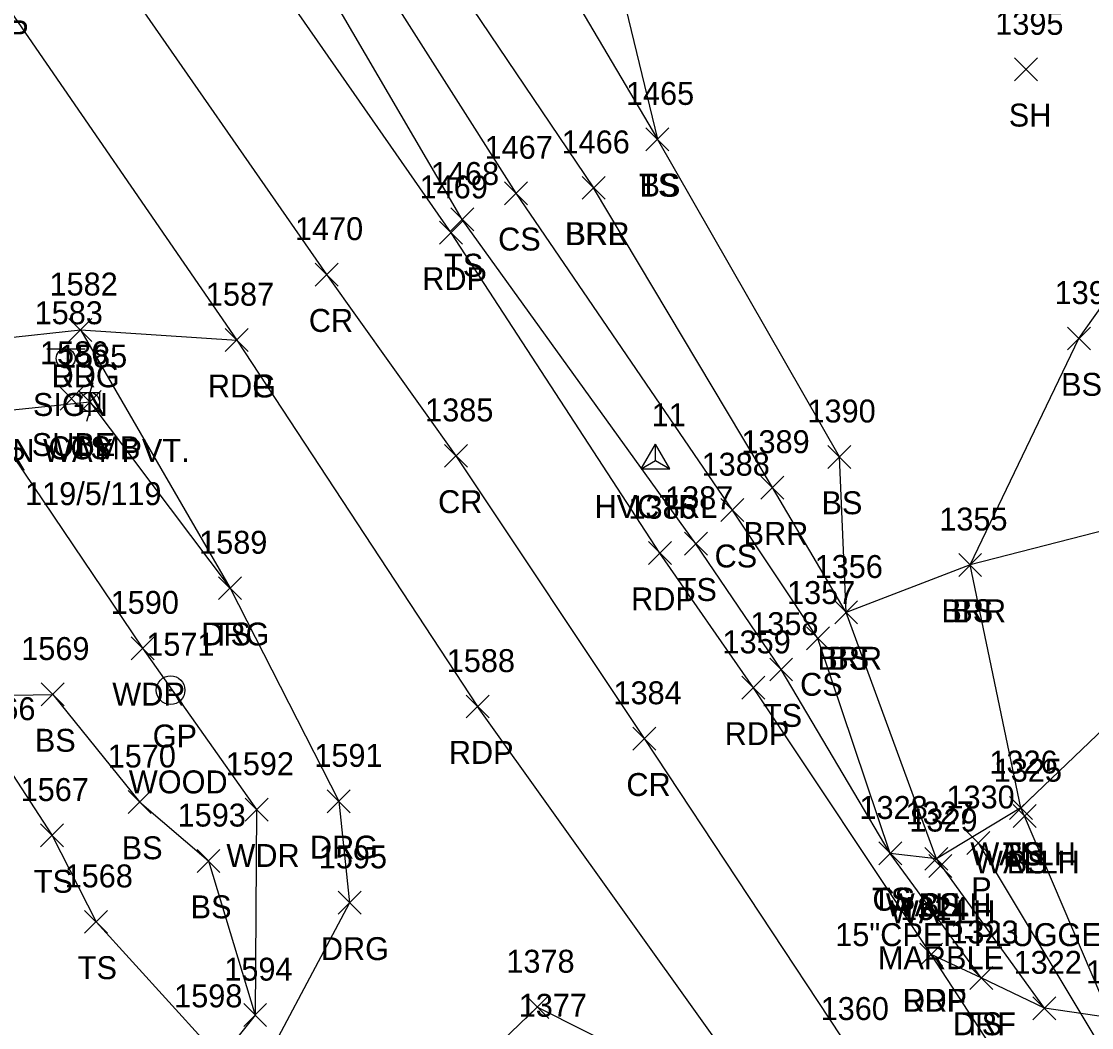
# Model space of a CAD drawing. Extents: x 1501299 to 1502485, y 381423 to 383765.
# Drawn here: x 1501656.9 to 1501750.2, y 383138.3 to 383226.1 of the extents above; entities that cross this region are included whole.
import ezdxf

# ---------------------------------------------------------------- set-up
doc = ezdxf.new("R2010")
doc.units = 0
for name, color, linetype in [('C_A', 7, 'Continuous'), ('C_I', 7, 'Continuous'), ('CPSM', 7, 'Continuous'), ('D_A', 7, 'Continuous'), ('D_C', 7, 'Continuous'), ('D_I', 7, 'Continuous'), ('D_TIC', 7, 'Continuous'), ('DCP', 7, 'Continuous'), ('DHW', 7, 'Continuous'), ('L_A', 7, 'Continuous'), ('L_I', 7, 'Continuous'), ('L_TIC', 7, 'Continuous'), ('LABL', 7, 'Continuous'), ('LAWA', 7, 'Continuous'), ('LELB', 7, 'Continuous'), ('P_A', 7, 'Continuous'), ('P_I', 7, 'Continuous'), ('P_TIC', 7, 'Continuous'), ('PET', 7, 'Continuous'), ('PEU', 7, 'Continuous'), ('PRC', 7, 'Continuous'), ('R_A', 7, 'Continuous'), ('R_C', 7, 'Continuous'), ('R_I', 7, 'Continuous'), ('R_TIC', 7, 'Continuous'), ('RDF', 7, 'Continuous'), ('RDG', 7, 'Continuous'), ('RGP', 7, 'Continuous'), ('S_A', 7, 'Continuous'), ('S_C', 7, 'Continuous'), ('S_I', 7, 'Continuous'), ('SSGN', 7, 'Continuous'), ('U_A', 7, 'Continuous'), ('U_C', 7, 'Continuous'), ('U_I', 7, 'Continuous'), ('U_TIC', 7, 'Continuous'), ('UP', 7, 'Continuous')]:
    doc.layers.add(name, color=color, linetype=linetype)

msp = doc.modelspace()

# ---------------------------------------------------------------- linework, layer by layer
at = {"layer": 'CPSM'}
for p, q in [((1501710.948, 383187.056), (1501712.198, 383189.221)), ((1501713.448, 383187.056), (1501712.198, 383189.221)), ((1501712.198, 383187.777), (1501712.198, 383189.221)), ((1501710.948, 383187.056), (1501712.198, 383187.777)), ((1501712.198, 383187.777), (1501712.198, 383187.777)), ((1501712.198, 383187.777), (1501713.448, 383187.056)), ((1501710.948, 383187.056), (1501713.448, 383187.056))]:
    msp.add_line(p, q, dxfattribs=at)
at = {"layer": 'D_TIC'}
for points in [[(1501743.066, 383156.494), (1501745.066, 383158.494)], [(1501745.066, 383156.494), (1501743.066, 383158.494)], [(1501743.392, 383155.782), (1501745.392, 383157.782)], [(1501745.392, 383155.782), (1501743.392, 383157.782)], [(1501739.356, 383153.447), (1501741.356, 383155.447)], [(1501741.356, 383153.447), (1501739.356, 383155.447)], [(1501735.699, 383152.056), (1501737.699, 383154.056)], [(1501737.699, 383152.056), (1501735.699, 383154.056)], [(1501736.043, 383151.433), (1501738.043, 383153.433)], [(1501738.043, 383151.433), (1501736.043, 383153.433)]]:
    msp.add_lwpolyline(points, dxfattribs=at)
at = {"layer": 'DCP'}
msp.add_lwpolyline([(1501761.064, 383119.969), (1501740.356, 383154.447)], dxfattribs=at)
at = {"layer": 'DHW'}
msp.add_lwpolyline([(1501744.392, 383156.782), (1501744.066, 383157.494), (1501736.699, 383153.056), (1501737.043, 383152.433)], dxfattribs=at)
at = {"layer": 'L_TIC'}
for points in [[(1501743.522, 383220.908), (1501745.522, 383222.908)], [(1501745.522, 383220.908), (1501743.522, 383222.908)], [(1501711.368, 383214.799), (1501713.368, 383216.799)], [(1501713.368, 383214.799), (1501711.368, 383216.799)], [(1501711.368, 383214.799), (1501713.368, 383216.799)], [(1501713.368, 383214.799), (1501711.368, 383216.799)], [(1501711.368, 383214.799), (1501713.368, 383216.799)], [(1501713.368, 383214.799), (1501711.368, 383216.799)], [(1501705.813, 383210.569), (1501707.813, 383212.569)], [(1501707.813, 383210.569), (1501705.813, 383212.569)], [(1501705.813, 383210.569), (1501707.813, 383212.569)], [(1501707.813, 383210.569), (1501705.813, 383212.569)], [(1501699.045, 383210.098), (1501701.045, 383212.098)], [(1501701.045, 383210.098), (1501699.045, 383212.098)], [(1501694.363, 383207.817), (1501696.363, 383209.817)], [(1501696.363, 383207.817), (1501694.363, 383209.817)], [(1501748.13, 383197.431), (1501750.13, 383199.431)], [(1501750.13, 383197.431), (1501748.13, 383199.431)], [(1501661.887, 383191.897), (1501663.887, 383193.897)], [(1501663.887, 383191.897), (1501661.887, 383193.897)], [(1501727.238, 383187.105), (1501729.238, 383189.105)], [(1501729.238, 383187.105), (1501727.238, 383189.105)], [(1501721.4, 383184.429), (1501723.4, 383186.429)], [(1501723.4, 383184.429), (1501721.4, 383186.429)], [(1501717.918, 383182.465), (1501719.918, 383184.465)], [(1501719.918, 383182.465), (1501717.918, 383184.465)], [(1501714.733, 383179.538), (1501716.733, 383181.538)], [(1501716.733, 383179.538), (1501714.733, 383181.538)], [(1501738.644, 383177.686), (1501740.644, 383179.686)], [(1501740.644, 383177.686), (1501738.644, 383179.686)], [(1501738.644, 383177.686), (1501740.644, 383179.686)], [(1501740.644, 383177.686), (1501738.644, 383179.686)], [(1501674.115, 383175.658), (1501676.115, 383177.658)], [(1501676.115, 383175.658), (1501674.115, 383177.658)], [(1501727.83, 383173.545), (1501729.83, 383175.545)], [(1501729.83, 383173.545), (1501727.83, 383175.545)], [(1501727.83, 383173.545), (1501729.83, 383175.545)], [(1501729.83, 383173.545), (1501727.83, 383175.545)], [(1501725.373, 383171.274), (1501727.373, 383173.274)], [(1501727.373, 383171.274), (1501725.373, 383173.274)], [(1501666.482, 383170.418), (1501668.482, 383172.418)], [(1501668.482, 383170.418), (1501666.482, 383172.418)], [(1501722.163, 383168.564), (1501724.163, 383170.564)], [(1501724.163, 383168.564), (1501722.163, 383170.564)], [(1501658.65, 383166.393), (1501660.65, 383168.393)], [(1501660.65, 383166.393), (1501658.65, 383168.393)], [(1501666.223, 383157.02), (1501668.223, 383159.02)], [(1501668.223, 383157.02), (1501666.223, 383159.02)], [(1501743.066, 383156.494), (1501745.066, 383158.494)], [(1501745.066, 383156.494), (1501743.066, 383158.494)], [(1501743.066, 383156.494), (1501745.066, 383158.494)], [(1501745.066, 383156.494), (1501743.066, 383158.494)], [(1501676.43, 383156.35), (1501678.43, 383158.35)], [(1501678.43, 383156.35), (1501676.43, 383158.35)], [(1501743.392, 383155.782), (1501745.392, 383157.782)], [(1501745.392, 383155.782), (1501743.392, 383157.782)], [(1501658.593, 383154.097), (1501660.593, 383156.097)], [(1501660.593, 383154.097), (1501658.593, 383156.097)], [(1501672.232, 383151.87), (1501674.232, 383153.87)], [(1501674.232, 383151.87), (1501672.232, 383153.87)], [(1501731.682, 383152.534), (1501733.682, 383154.534)], [(1501733.682, 383152.534), (1501731.682, 383154.534)], [(1501731.682, 383152.534), (1501733.682, 383154.534)], [(1501733.682, 383152.534), (1501731.682, 383154.534)], [(1501735.699, 383152.056), (1501737.699, 383154.056)], [(1501737.699, 383152.056), (1501735.699, 383154.056)], [(1501735.699, 383152.056), (1501737.699, 383154.056)], [(1501737.699, 383152.056), (1501735.699, 383154.056)], [(1501662.428, 383146.565), (1501664.428, 383148.565)], [(1501664.428, 383146.565), (1501662.428, 383148.565)], [(1501739.606, 383141.674), (1501741.606, 383143.674)], [(1501741.606, 383141.674), (1501739.606, 383143.674)], [(1501745.121, 383139.03), (1501747.121, 383141.03)], [(1501747.121, 383139.03), (1501745.121, 383141.03)], [(1501676.301, 383138.435), (1501678.301, 383140.435)], [(1501678.301, 383138.435), (1501676.301, 383140.435)], [(1501676.301, 383138.435), (1501678.301, 383140.435)], [(1501678.301, 383138.435), (1501676.301, 383140.435)]]:
    msp.add_lwpolyline(points, dxfattribs=at)
at = {"layer": 'LABL'}
for points in [[(1501676.933, 383259.602), (1501687.201, 383240.603), (1501706.813, 383211.569)], [(1501829.407, 383246.711), (1501798.883, 383237.177), (1501788.348, 383224.288), (1501778.275, 383209.226), (1501772.667, 383194.977), (1501763.707, 383179.067), (1501752.776, 383182.053), (1501739.644, 383178.686), (1501728.83, 383174.545), (1501722.4, 383185.429), (1501706.813, 383211.569)]]:
    msp.add_lwpolyline(points, dxfattribs=at)
at = {"layer": 'LAWA'}
msp.add_lwpolyline([(1501548.16, 383146.636), (1501571.521, 383160.277), (1501598.465, 383173.707), (1501618.343, 383183.177), (1501640.684, 383191.304), (1501653.606, 383191.947), (1501667.482, 383171.418), (1501677.43, 383157.35), (1501677.301, 383139.435), (1501665.744, 383124.938), (1501648.242, 383107.593), (1501635.222, 383093.489)], dxfattribs=at)
at = {"layer": 'LELB'}
for points in [[(1501740.606, 383142.674), (1501732.682, 383153.534), (1501723.163, 383169.564), (1501715.733, 383180.538), (1501695.363, 383208.817), (1501677.401, 383239.568), (1501666.231, 383254.465), (1501657.204, 383265.279), (1501647.762, 383280.285), (1501635.957, 383296.227)], [(1501736.699, 383153.056), (1501732.682, 383153.534), (1501726.373, 383172.274), (1501718.918, 383183.465), (1501700.045, 383211.098), (1501680.296, 383242.203), (1501669.093, 383257.5), (1501660.991, 383268.478), (1501649.565, 383283.093), (1501640.692, 383295.782)], [(1501680.172, 383293.143), (1501684.978, 383277.331), (1501691.264, 383265.233), (1501705.726, 383243.318), (1501712.368, 383215.799)], [(1501673.639, 383291.799), (1501678.935, 383275.649), (1501684.674, 383261.78), (1501696.874, 383242.078), (1501712.368, 383215.799)], [(1501744.066, 383157.494), (1501739.644, 383178.686), (1501749.13, 383198.431), (1501757.23, 383209.844), (1501762.675, 383226.957), (1501780.065, 383240.141), (1501796.792, 383256.727)], [(1501744.066, 383157.494), (1501754.689, 383167.681), (1501752.776, 383182.053), (1501755.187, 383195.987), (1501761.593, 383208.768), (1501770.997, 383222.876), (1501783.301, 383233.77), (1501801.073, 383247.027), (1501816.316, 383251.234)], [(1501746.121, 383140.03), (1501736.699, 383153.056), (1501728.83, 383174.545), (1501728.238, 383188.105), (1501712.368, 383215.799)], [(1501653.606, 383191.947), (1501662.887, 383192.897), (1501675.115, 383176.658)], [(1501644.096, 383167.132), (1501659.65, 383167.393), (1501667.223, 383158.02), (1501673.232, 383152.87), (1501677.301, 383139.435)], [(1501574.387, 383130.876), (1501576.88, 383137.239), (1501587.123, 383134.548), (1501591.981, 383125.923), (1501605.906, 383116.295), (1501617.184, 383118.06), (1501635.069, 383129.084), (1501644.679, 383143.095), (1501638.019, 383150.194), (1501648.46, 383156.854), (1501654.993, 383162.146), (1501659.593, 383155.097), (1501663.428, 383147.565), (1501672.931, 383137.106), (1501665.744, 383124.938)], [(1501751.867, 383139.198), (1501744.392, 383156.782)]]:
    msp.add_lwpolyline(points, dxfattribs=at)
at = {"layer": 'P_TIC'}
for points in [[(1501693.383, 383206.646), (1501695.383, 383208.646)], [(1501695.383, 383206.646), (1501693.383, 383208.646)], [(1501682.547, 383203.004), (1501684.547, 383205.004)], [(1501684.547, 383203.004), (1501682.547, 383205.004)], [(1501661.064, 383198.174), (1501663.064, 383200.174)], [(1501663.064, 383198.174), (1501661.064, 383200.174)], [(1501674.697, 383197.288), (1501676.697, 383199.288)], [(1501676.697, 383197.288), (1501674.697, 383199.288)], [(1501674.697, 383197.288), (1501676.697, 383199.288)], [(1501676.697, 383197.288), (1501674.697, 383199.288)], [(1501693.816, 383187.199), (1501695.816, 383189.199)], [(1501695.816, 383187.199), (1501693.816, 383189.199)], [(1501711.594, 383178.719), (1501713.594, 383180.719)], [(1501713.594, 383178.719), (1501711.594, 383180.719)], [(1501719.749, 383166.971), (1501721.749, 383168.971)], [(1501721.749, 383166.971), (1501719.749, 383168.971)], [(1501695.699, 383165.339), (1501697.699, 383167.339)], [(1501697.699, 383165.339), (1501695.699, 383167.339)], [(1501695.699, 383165.339), (1501697.699, 383167.339)], [(1501697.699, 383165.339), (1501695.699, 383167.339)], [(1501710.236, 383162.535), (1501712.236, 383164.535)], [(1501712.236, 383162.535), (1501710.236, 383164.535)], [(1501735.241, 383143.717), (1501737.241, 383145.717)], [(1501737.241, 383143.717), (1501735.241, 383145.717)]]:
    msp.add_lwpolyline(points, dxfattribs=at)
at = {"layer": 'PET'}
for points in [[(1501787.994, 383066.094), (1501768.484, 383096.751), (1501754.41, 383116.891), (1501736.241, 383144.717), (1501720.749, 383167.971), (1501712.594, 383179.719), (1501694.383, 383207.646), (1501673.597, 383237.523), (1501647.754, 383273.845), (1501633.679, 383294.635), (1501626.393, 383287.881), (1501619.162, 383281.8), (1501626.926, 383271.201), (1501654.425, 383229.168), (1501675.697, 383198.288), (1501696.699, 383166.339)], [(1501949.648, 382716.507), (1501941.04, 382745.977), (1501925.012, 382788.592), (1501904.253, 382831.621), (1501880.763, 382877.887), (1501870.565, 382894.723), (1501847.406, 382934.273), (1501830.938, 382961.01), (1501807.981, 382997.987), (1501787.075, 383029.946), (1501762.257, 383068.782), (1501737.378, 383106.292), (1501722.895, 383129.668), (1501696.699, 383166.339)]]:
    msp.add_lwpolyline(points, dxfattribs=at)
at = {"layer": 'PEU'}
msp.add_lwpolyline([(1501544.062, 383151.179), (1501570.929, 383164.395), (1501598.867, 383177.895), (1501615.32, 383186.884), (1501641.204, 383196.915), (1501662.064, 383199.174), (1501675.697, 383198.288)], dxfattribs=at)
at = {"layer": 'PRC'}
msp.add_lwpolyline([(1501960.612, 382718.648), (1501950.96, 382750.482), (1501934.965, 382791.852), (1501913.074, 382836.935), (1501889.309, 382881.383), (1501879.244, 382899.507), (1501856.391, 382940.32), (1501839.674, 382966.998), (1501816.055, 383004.313), (1501794.783, 383036.247), (1501769.812, 383075.158), (1501745.791, 383111.558), (1501729.435, 383136.001), (1501711.236, 383163.535), (1501694.816, 383188.199), (1501683.547, 383204.004), (1501664.644, 383231.239), (1501639.517, 383268.342), (1501626.393, 383287.881)], dxfattribs=at)
at = {"layer": 'R_TIC'}
for points in [[(1501661.064, 383198.174), (1501663.064, 383200.174)], [(1501663.064, 383198.174), (1501661.064, 383200.174)], [(1501674.115, 383175.658), (1501676.115, 383177.658)], [(1501676.115, 383175.658), (1501674.115, 383177.658)], [(1501683.586, 383157.077), (1501685.586, 383159.077)], [(1501685.586, 383157.077), (1501683.586, 383159.077)], [(1501684.539, 383148.226), (1501686.539, 383150.226)], [(1501686.539, 383148.226), (1501684.539, 383150.226)], [(1501735.241, 383143.717), (1501737.241, 383145.717)], [(1501737.241, 383143.717), (1501735.241, 383145.717)], [(1501739.606, 383141.674), (1501741.606, 383143.674)], [(1501741.606, 383141.674), (1501739.606, 383143.674)], [(1501700.897, 383139.126), (1501702.897, 383141.126)], [(1501702.897, 383139.126), (1501700.897, 383141.126)], [(1501745.121, 383139.03), (1501747.121, 383141.03)], [(1501747.121, 383139.03), (1501745.121, 383141.03)]]:
    msp.add_lwpolyline(points, dxfattribs=at)
at = {"layer": 'RDF'}
msp.add_lwpolyline([(1501826.267, 383146.591), (1501788.75, 383138.821), (1501766.44, 383136.412), (1501751.867, 383139.198), (1501746.121, 383140.03), (1501740.606, 383142.674), (1501736.241, 383144.717)], dxfattribs=at)
at = {"layer": 'RDG'}
for points in [[(1501662.064, 383199.174), (1501675.115, 383176.658), (1501684.586, 383158.077), (1501685.539, 383149.226), (1501676.082, 383131.445), (1501669.335, 383121.403), (1501658.131, 383102.109), (1501647.896, 383082.123)], [(1501722.895, 383129.668), (1501718.865, 383131.579), (1501701.897, 383140.126), (1501694.191, 383132.723), (1501687.272, 383121.659), (1501682.676, 383110.731), (1501680.878, 383103.605), (1501671.174, 383087.161), (1501662.91, 383067.619)]]:
    msp.add_lwpolyline(points, dxfattribs=at)
at = {"layer": 'RGP'}
msp.add_line((1501669.93, 383167.766), (1501669.93, 383167.766), dxfattribs=at)
for radius in [1.25, 0.0833]:
    msp.add_circle((1501669.93, 383167.766), radius, dxfattribs=at)
at = {"layer": 'SSGN'}
for p, q in [((1501659.138, 383197.527), (1501662.472, 383197.527)), ((1501660.785, 383196.693), (1501660.785, 383196.693))]:
    msp.add_line(p, q, dxfattribs=at)
msp.add_circle((1501660.785, 383196.693), 0.833, dxfattribs=at)
at = {"layer": 'U_TIC'}
for points in [[(1501660.29, 383192.179), (1501662.29, 383194.179)], [(1501662.29, 383192.179), (1501660.29, 383194.179)]]:
    msp.add_lwpolyline(points, dxfattribs=at)
at = {"layer": 'UP'}
for p, q in [((1501663.137, 383194.564), (1501662.887, 383193.73)), ((1501662.054, 383192.064), (1501662.054, 383193.73)), ((1501662.054, 383193.73), (1501663.721, 383193.73)), ((1501663.721, 383193.73), (1501663.721, 383192.064)), ((1501663.721, 383192.064), (1501662.054, 383192.064)), ((1501662.637, 383191.23), (1501662.887, 383192.064)), ((1501662.887, 383192.897), (1501662.887, 383192.897))]:
    msp.add_line(p, q, dxfattribs=at)
msp.add_circle((1501662.887, 383192.897), 0.833, dxfattribs=at)

# ---------------------------------------------------------------- texts
at = {"layer": 'C_A'}
msp.add_text('HVCTRL', height=2, dxfattribs=at).set_placement((1501706.891, 383182.777))
at = {"layer": 'C_I'}
msp.add_text('11', height=2, dxfattribs=at).set_placement((1501711.867, 383190.777))
at = {"layer": 'D_A'}
for s, p in [('WALLH', (1501739.657, 383152.494)), ('WALLH', (1501739.983, 383151.782)), ('P', (1501739.734, 383149.447)), ('WALLH', (1501732.289, 383148.056)), ('WALLH', (1501732.634, 383147.433))]:
    msp.add_text(s, height=2, dxfattribs=at).set_placement(p)
at = {"layer": 'D_C'}
for s, p in [('15"CPEP-PLUGGED', (1501727.876, 383145.447)), ('MARBLE', (1501731.594, 383143.433))]:
    msp.add_text(s, height=2, dxfattribs=at).set_placement(p)
at = {"layer": 'D_I'}
for s, p in [('1326', (1501741.319, 383160.494)), ('1325', (1501741.699, 383159.782)), ('1330', (1501737.577, 383157.447)), ('1327', (1501734.006, 383156.056)), ('1329', (1501734.342, 383155.433))]:
    msp.add_text(s, height=2, dxfattribs=at).set_placement(p)
at = {"layer": 'L_A'}
for s, p in [('SH', (1501743.01, 383216.908)), ('TS', (1501710.777, 383210.799)), ('BS', (1501710.809, 383210.799)), ('BS', (1501710.809, 383210.799)), ('CS', (1501698.486, 383206.098)), ('BRR', (1501704.301, 383206.569)), ('BRL', (1501704.356, 383206.569)), ('TS', (1501693.772, 383203.817)), ('BS', (1501747.571, 383193.431)), ('TS', (1501661.297, 383187.897)), ('WDR', (1501650.968, 383186.947)), ('BS', (1501726.679, 383183.105)), ('BRR', (1501719.888, 383180.429)), ('CS', (1501717.359, 383178.465)), ('TS', (1501714.143, 383175.538)), ('BRR', (1501737.132, 383173.686)), ('BS', (1501738.085, 383173.686)), ('TS', (1501673.524, 383171.658)), ('BRR', (1501726.318, 383169.545)), ('BS', (1501727.271, 383169.545)), ('CS', (1501724.814, 383167.274)), ('WDR', (1501664.844, 383166.418)), ('TS', (1501721.573, 383164.564)), ('BS', (1501658.091, 383162.393)), ('BS', (1501665.664, 383153.02)), ('WDR', (1501674.792, 383152.35)), ('TS', (1501742.476, 383152.494)), ('BS', (1501742.507, 383152.494)), ('BS', (1501742.833, 383151.782)), ('TS', (1501658.002, 383150.097)), ('TS', (1501731.091, 383148.534)), ('CS', (1501731.123, 383148.534)), ('CS', (1501735.14, 383148.056)), ('BS', (1501735.14, 383148.056)), ('BS', (1501671.673, 383147.87)), ('TS', (1501661.837, 383142.565)), ('TS', (1501739.016, 383137.674))]:
    msp.add_text(s, height=2, dxfattribs=at).set_placement(p)
at = {"layer": 'L_I'}
for s, p in [('1395', (1501741.829, 383224.908)), ('1465', (1501709.628, 383218.799)), ('1465', (1501709.628, 383218.799)), ('1465', (1501709.628, 383218.799)), ('1466', (1501704.018, 383214.569)), ('1466', (1501704.018, 383214.569)), ('1467', (1501697.305, 383214.098)), ('1468', (1501692.623, 383211.817)), ('1391', (1501747.004, 383201.431)), ('1585', (1501660.195, 383195.897)), ('1390', (1501725.458, 383191.105)), ('1389', (1501719.7, 383188.429)), ('1388', (1501716.226, 383186.465)), ('1387', (1501713.041, 383183.538)), ('1355', (1501736.951, 383181.686)), ('1355', (1501736.951, 383181.686)), ('1589', (1501672.414, 383179.658)), ('1356', (1501726.082, 383177.545)), ('1356', (1501726.082, 383177.545)), ('1357', (1501723.68, 383175.274)), ('1590', (1501664.702, 383174.418)), ('1358', (1501720.471, 383172.564)), ('1569', (1501656.903, 383170.393)), ('1566', (1501652.197, 383165.146)), ('1570', (1501664.443, 383161.02)), ('1592', (1501674.737, 383160.35)), ('1326', (1501741.319, 383160.494)), ('1326', (1501741.319, 383160.494)), ('1325', (1501741.699, 383159.782)), ('1567', (1501656.853, 383158.097)), ('1328', (1501729.989, 383156.534)), ('1328', (1501729.989, 383156.534)), ('1593', (1501670.539, 383155.87)), ('1327', (1501734.006, 383156.056)), ('1327', (1501734.006, 383156.056)), ('1568', (1501660.688, 383150.565)), ('1323', (1501737.913, 383145.674)), ('1594', (1501674.609, 383142.435)), ('1594', (1501674.609, 383142.435)), ('1322', (1501743.428, 383143.03)), ('1321', (1501749.742, 383142.198)), ('1598', (1501670.238, 383140.106)), ('1377', (1501700.284, 383139.285))]:
    msp.add_text(s, height=2, dxfattribs=at).set_placement(p)
at = {"layer": 'P_A'}
for s, p in [('RDP', (1501651.913, 383224.168)), ('RDP', (1501691.871, 383202.646)), ('CR', (1501681.98, 383199.004)), ('RDG', (1501659.552, 383194.174)), ('RDG', (1501673.185, 383193.288)), ('RDP', (1501673.185, 383193.288)), ('CR', (1501693.249, 383183.199)), ('RDP', (1501710.082, 383174.719)), ('RDP', (1501718.237, 383162.971)), ('RDP', (1501694.187, 383161.339)), ('RDP', (1501694.187, 383161.339)), ('CR', (1501709.669, 383158.535)), ('RDP', (1501733.73, 383139.717))]:
    msp.add_text(s, height=2, dxfattribs=at).set_placement(p)
at = {"layer": 'P_I'}
for s, p in [('1469', (1501691.635, 383210.646)), ('1470', (1501680.768, 383207.004)), ('1582', (1501659.371, 383202.174)), ('1587', (1501673.005, 383201.288)), ('1587', (1501673.005, 383201.288)), ('1385', (1501692.123, 383191.199)), ('1386', (1501709.846, 383182.719)), ('1359', (1501718.048, 383170.971)), ('1588', (1501694.006, 383169.339)), ('1588', (1501694.006, 383169.339)), ('1384', (1501708.543, 383166.535)), ('1324', (1501733.549, 383147.717)), ('1360', (1501726.608, 383139.001))]:
    msp.add_text(s, height=2, dxfattribs=at).set_placement(p)
at = {"layer": 'R_A'}
for s, p in [('DRG', (1501659.552, 383194.174)), ('DRG', (1501672.603, 383171.658)), ('GP', (1501668.364, 383162.766)), ('DRG', (1501682.074, 383153.077)), ('DRG', (1501683.028, 383144.226)), ('DRF', (1501733.777, 383139.717)), ('DRF', (1501738.141, 383137.674))]:
    msp.add_text(s, height=2, dxfattribs=at).set_placement(p)
at = {"layer": 'R_C'}
msp.add_text('WOOD', height=2, dxfattribs=at).set_placement((1501666.285, 383158.766))
at = {"layer": 'R_I'}
for s, p in [('1582', (1501659.371, 383202.174)), ('1589', (1501672.414, 383179.658)), ('1571', (1501667.805, 383170.766)), ('1591', (1501682.46, 383161.077)), ('1595', (1501682.847, 383152.226)), ('1324', (1501733.549, 383147.717)), ('1323', (1501737.913, 383145.674)), ('1378', (1501699.204, 383143.126)), ('1322', (1501743.428, 383143.03)), ('1321', (1501749.742, 383142.198))]:
    msp.add_text(s, height=2, dxfattribs=at).set_placement(p)
at = {"layer": 'S_A'}
msp.add_text('SIGN', height=2, dxfattribs=at).set_placement((1501657.923, 383191.673))
at = {"layer": 'S_C'}
msp.add_text('BOWEN WAY PVT.', height=2, dxfattribs=at).set_placement((1501647.963, 383187.673))
at = {"layer": 'S_I'}
msp.add_text('1583', height=2, dxfattribs=at).set_placement((1501658.073, 383199.673))
at = {"layer": 'U_A'}
for s, p in [('SUBE', (1501657.825, 383188.179)), ('COMB', (1501659.273, 383187.897))]:
    msp.add_text(s, height=2, dxfattribs=at).set_placement(p)
at = {"layer": 'U_C'}
msp.add_text('119/5/119', height=2, dxfattribs=at).set_placement((1501657.242, 383183.897))
at = {"layer": 'U_I'}
for s, p in [('1586', (1501658.542, 383196.179)), ('1585', (1501660.195, 383195.897))]:
    msp.add_text(s, height=2, dxfattribs=at).set_placement(p)

doc.saveas('drawing.dxf')
